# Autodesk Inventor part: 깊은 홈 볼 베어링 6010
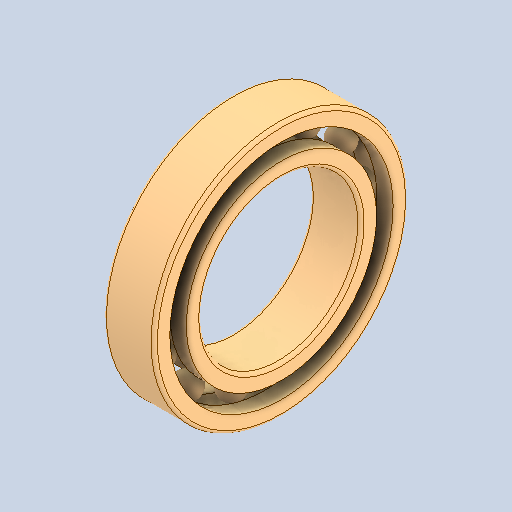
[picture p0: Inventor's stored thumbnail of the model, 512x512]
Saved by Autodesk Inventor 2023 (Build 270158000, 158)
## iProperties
Created: 2026-04
Part Number: 깊은 홈 볼 베어링 6010
Material: 강철, 연강
Description: 깊은 그루브 볼 베어링
Document SubType Name: Modeling
Designer: home
Density: 7.85 g/cm^3
Appearance: 기본값
Author: jhkim
Sending System: Autodesk Inventor 2027
Preprocessor: ST-DEVELOPER v20.1
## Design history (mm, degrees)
feature "Solid1"
feature "Solid1:1"
feature "Solid1:2"
feature "Solid1:3"
feature "Solid1:4"
feature "Solid1:5"
feature "Solid1:6"
feature "Solid1:7"
feature "Solid1:8"
feature "Solid1:9"
feature "Solid1:10"
feature "Solid1:11"
feature "Solid1:12"
feature "Solid1:13"
feature "Solid1:14"
node "솔리드1"
node "솔리드2"
node "솔리드3"
node "솔리드4"
node "솔리드5"
node "솔리드6"
node "솔리드7"
node "솔리드8"
node "솔리드9"
node "솔리드10"
node "솔리드11"
node "솔리드12"
node "솔리드13"
node "솔리드14"
node "솔리드15"
